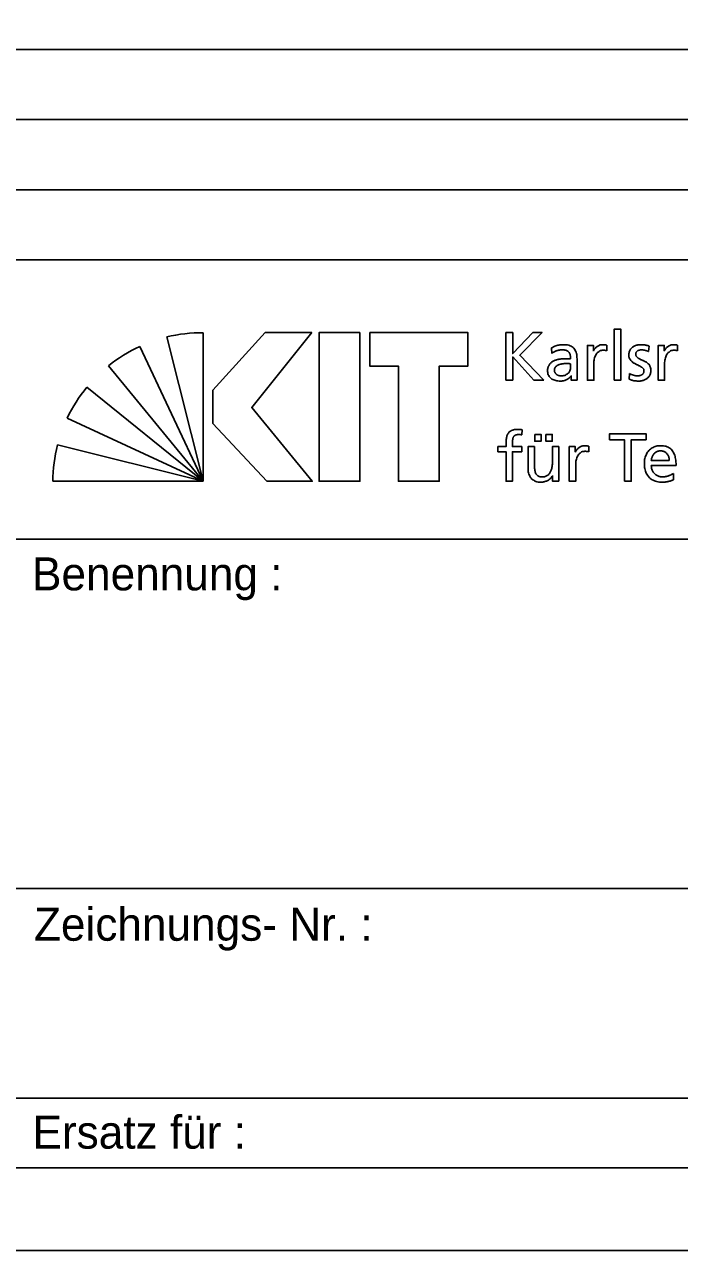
# Model space of a CAD drawing. Extents: x 0 to 210, y 0 to 148.
# Drawn here: x 188.16 to 198.08, y 0 to 18.56 of the extents above; entities that cross this region are included whole.
import ezdxf

# ---------------------------------------------------------------- set-up
doc = ezdxf.new("R2010")
doc.units = 0
doc.layers.add('90_Plankopf', color=7, linetype='Continuous')

msp = doc.modelspace()

# ---------------------------------------------------------------- linework, layer by layer
at = {"layer": '90_Plankopf'}
for p, q in [((164.53, 18.185), (209, 18.185)), ((164.53, 17.123), (209, 17.123)), ((164.53, 16.06), (209, 16.06)), ((164.53, 14.998), (209, 14.998)), ((164.53, 14.998), (209, 14.998)), ((190.319, 13.833), (190.87, 11.647)), ((190.87, 11.647), (190.87, 13.896)), ((195.452, 13.897), (195.452, 13.176)), ((190.87, 11.647), (189.908, 13.688)), ((196.145, 13.665), (196.15, 13.583)), ((196.982, 13.621), (196.982, 13.708)), ((197.614, 13.61), (197.622, 13.694)), ((198.053, 13.621), (198.053, 13.708)), ((189.436, 13.396), (190.87, 11.647)), ((196.433, 13.427), (196.433, 13.381)), ((196.53, 13.28), (196.53, 13.497)), ((197.324, 13.28), (197.319, 13.193)), ((190.87, 11.647), (189.108, 13.071)), ((195.452, 13.176), (195.556, 13.176)), ((195.876, 13.176), (196.027, 13.176)), ((188.81, 12.603), (190.87, 11.647)), ((195.693, 12.348), (195.697, 12.427)), ((190.87, 11.647), (188.664, 12.197)), ((196.707, 12.091), (196.707, 12.178)), ((197.927, 11.96), (197.654, 11.96)), ((197.654, 11.888), (198.03, 11.888)), ((197.989, 11.668), (197.989, 11.765)), ((188.591, 11.647), (190.87, 11.647)), ((188, 10.768), (209, 10.768)), ((188, 5.48), (209, 5.48)), ((188, 2.308), (209, 2.308)), ((209, 1.25), (164.53, 1.25)), ((167.45, 1.25), (209, 1.25)), ((167.45, 1.25), (209, 1.25))]:
    msp.add_line(p, q, dxfattribs=at)
for points in [[(0, 0), (210.25, 0), (210.25, 148.5), (0, 148.5)], [(6.25, 147.25), (209, 147.25), (209, 1.25), (6.25, 1.25)], [(192.517, 13.897), (191.809, 13.897), (191.018, 13.025), (191.018, 12.523), (191.834, 11.647), (192.521, 11.647), (191.606, 12.766)], [(193.243, 13.897), (193.243, 11.647), (192.625, 11.647), (192.625, 13.897)], [(193.391, 13.897), (193.391, 13.39), (193.825, 13.39), (193.825, 11.647), (194.443, 11.647), (194.443, 13.39), (194.877, 13.39), (194.877, 13.897)]]:
    msp.add_lwpolyline(points, close=True, dxfattribs=at)
for points in [[(197.095, 13.176), (197.192, 13.176), (197.192, 13.95), (197.095, 13.95), (197.095, 13.176)], [(196.027, 13.176), (195.662, 13.556), (196, 13.897), (195.863, 13.897), (195.556, 13.58), (195.556, 13.897), (195.452, 13.897)], [(196.78, 13.621), (196.778, 13.621), (196.778, 13.703), (196.688, 13.703), (196.688, 13.176), (196.785, 13.176), (196.785, 13.416)], [(197.852, 13.621), (197.85, 13.621), (197.85, 13.703), (197.759, 13.703), (197.759, 13.176), (197.856, 13.176), (197.856, 13.416)], [(195.556, 13.176), (195.556, 13.529), (195.876, 13.176)], [(196.441, 13.245), (196.443, 13.245), (196.443, 13.176), (196.534, 13.176)], [(195.889, 12.356), (195.889, 12.253), (195.986, 12.253), (195.986, 12.356), (195.889, 12.356)], [(196.058, 12.356), (196.058, 12.253), (196.155, 12.253), (196.155, 12.356), (196.058, 12.356)], [(197.248, 11.647), (197.351, 11.647), (197.351, 12.276), (197.575, 12.276), (197.575, 12.367), (197.024, 12.367), (197.024, 12.276), (197.248, 12.276), (197.248, 11.647)], [(195.456, 12.221), (195.456, 12.173), (195.332, 12.173), (195.332, 12.094), (195.456, 12.094), (195.456, 11.647), (195.553, 11.647), (195.553, 12.094), (195.692, 12.094), (195.692, 12.173), (195.553, 12.173), (195.553, 12.23)], [(195.885, 11.9), (195.885, 12.173), (195.788, 12.173), (195.788, 11.86)], [(196.254, 11.647), (196.254, 12.173), (196.157, 12.173), (196.157, 11.929)], [(196.506, 12.091), (196.504, 12.091), (196.504, 12.173), (196.413, 12.173), (196.413, 11.647), (196.51, 11.647), (196.51, 11.886)], [(196.158, 11.73), (196.16, 11.73), (196.16, 11.647), (196.254, 11.647)]]:
    msp.add_lwpolyline(points, dxfattribs=at)
for centre, start, end in [((190.862, 11.514), 89.8053, 103.1895), ((190.915, 11.529), 115.0126, 128.3968), ((190.954, 11.566), 140.7898, 154.174), ((190.973, 11.609), 165.7222, 179.1064)]:
    msp.add_arc(centre, 2.382, start, end, dxfattribs=at)
for points in [[(196.53, 13.497), (196.53, 13.545), (196.523, 13.585), (196.508, 13.617), (196.494, 13.65), (196.471, 13.674), (196.44, 13.69), (196.409, 13.707), (196.368, 13.715), (196.318, 13.715), (196.285, 13.715), (196.253, 13.71), (196.224, 13.701), (196.195, 13.692), (196.169, 13.68), (196.145, 13.665)], [(196.15, 13.583), (196.163, 13.594), (196.178, 13.604), (196.195, 13.611), (196.211, 13.62), (196.229, 13.626), (196.247, 13.63), (196.266, 13.634), (196.284, 13.637), (196.303, 13.637), (196.335, 13.637), (196.36, 13.631), (196.379, 13.621), (196.399, 13.611), (196.412, 13.596), (196.42, 13.575), (196.429, 13.555), (196.433, 13.53), (196.433, 13.499)], [(196.982, 13.708), (196.975, 13.709), (196.968, 13.71), (196.962, 13.712), (196.956, 13.713), (196.949, 13.713), (196.942, 13.714), (196.935, 13.715), (196.927, 13.715), (196.918, 13.715), (196.899, 13.715), (196.881, 13.711), (196.863, 13.703), (196.845, 13.695), (196.829, 13.684), (196.815, 13.67), (196.801, 13.656), (196.789, 13.639), (196.78, 13.621)], [(196.785, 13.416), (196.785, 13.46), (196.791, 13.498), (196.802, 13.53), (196.814, 13.562), (196.831, 13.587), (196.852, 13.604), (196.874, 13.621), (196.899, 13.63), (196.928, 13.63), (196.936, 13.631), (196.945, 13.63), (196.954, 13.629), (196.964, 13.627), (196.973, 13.625), (196.982, 13.621)], [(197.622, 13.694), (197.604, 13.7), (197.584, 13.705), (197.565, 13.709), (197.545, 13.713), (197.524, 13.715), (197.502, 13.715), (197.476, 13.715), (197.451, 13.712), (197.429, 13.705), (197.406, 13.698), (197.387, 13.688), (197.37, 13.675), (197.353, 13.662), (197.34, 13.645), (197.33, 13.625), (197.321, 13.604), (197.316, 13.58), (197.316, 13.553), (197.316, 13.532), (197.321, 13.514), (197.329, 13.498), (197.337, 13.483), (197.348, 13.47), (197.361, 13.459), (197.375, 13.447), (197.39, 13.437), (197.406, 13.429), (197.422, 13.42), (197.438, 13.412), (197.454, 13.404), (197.471, 13.397), (197.485, 13.389), (197.499, 13.38), (197.512, 13.373), (197.523, 13.363), (197.532, 13.353), (197.54, 13.343), (197.544, 13.331), (197.544, 13.318), (197.544, 13.304), (197.541, 13.292), (197.535, 13.282), (197.529, 13.272), (197.521, 13.265), (197.511, 13.259), (197.501, 13.253), (197.491, 13.249), (197.479, 13.246), (197.468, 13.244), (197.456, 13.242), (197.445, 13.242), (197.435, 13.242), (197.424, 13.244), (197.41, 13.247), (197.396, 13.249), (197.381, 13.253), (197.366, 13.259), (197.351, 13.265), (197.337, 13.271), (197.324, 13.28)], [(197.319, 13.193), (197.342, 13.181), (197.365, 13.174), (197.389, 13.17), (197.414, 13.166), (197.439, 13.164), (197.464, 13.164), (197.487, 13.164), (197.51, 13.167), (197.532, 13.174), (197.554, 13.18), (197.573, 13.191), (197.591, 13.204), (197.608, 13.217), (197.622, 13.234), (197.632, 13.255), (197.642, 13.276), (197.647, 13.3), (197.647, 13.328), (197.647, 13.352), (197.643, 13.372), (197.635, 13.389), (197.626, 13.406), (197.616, 13.42), (197.602, 13.431), (197.589, 13.443), (197.574, 13.453), (197.557, 13.461), (197.541, 13.469), (197.525, 13.477), (197.509, 13.484), (197.493, 13.491), (197.478, 13.499), (197.464, 13.507), (197.451, 13.515), (197.44, 13.524), (197.432, 13.534), (197.424, 13.545), (197.419, 13.557), (197.419, 13.573), (197.419, 13.587), (197.424, 13.599), (197.432, 13.609), (197.441, 13.618), (197.452, 13.625), (197.466, 13.63), (197.48, 13.634), (197.495, 13.637), (197.512, 13.637), (197.518, 13.637), (197.526, 13.636), (197.535, 13.634), (197.544, 13.633), (197.553, 13.631), (197.564, 13.628), (197.574, 13.626), (197.583, 13.623), (197.592, 13.62), (197.601, 13.616), (197.609, 13.613), (197.614, 13.61)], [(198.053, 13.708), (198.046, 13.709), (198.04, 13.71), (198.034, 13.712), (198.027, 13.713), (198.021, 13.713), (198.014, 13.714), (198.007, 13.715), (197.998, 13.715), (197.989, 13.715), (197.97, 13.715), (197.952, 13.711), (197.934, 13.703), (197.917, 13.695), (197.901, 13.684), (197.886, 13.67), (197.872, 13.656), (197.86, 13.639), (197.852, 13.621)], [(197.856, 13.416), (197.856, 13.46), (197.862, 13.498), (197.874, 13.53), (197.886, 13.562), (197.902, 13.587), (197.923, 13.604), (197.945, 13.621), (197.97, 13.63), (197.999, 13.63), (198.008, 13.631), (198.016, 13.63), (198.026, 13.629), (198.035, 13.627), (198.044, 13.625), (198.053, 13.621)], [(196.433, 13.499), (196.42, 13.5), (196.408, 13.501), (196.397, 13.501), (196.386, 13.501), (196.376, 13.501), (196.365, 13.501), (196.354, 13.501), (196.342, 13.501), (196.329, 13.501), (196.309, 13.501), (196.288, 13.5), (196.266, 13.496), (196.243, 13.492), (196.221, 13.487), (196.2, 13.478), (196.179, 13.47), (196.16, 13.46), (196.142, 13.446), (196.125, 13.433), (196.111, 13.416), (196.101, 13.397), (196.09, 13.377), (196.085, 13.354), (196.085, 13.328), (196.085, 13.29), (196.094, 13.259), (196.11, 13.235), (196.126, 13.211), (196.149, 13.193), (196.177, 13.181), (196.206, 13.17), (196.24, 13.164), (196.278, 13.164), (196.3, 13.164), (196.32, 13.167), (196.338, 13.172), (196.355, 13.177), (196.371, 13.184), (196.384, 13.192), (196.398, 13.2), (196.409, 13.209), (196.418, 13.218), (196.428, 13.228), (196.435, 13.236), (196.441, 13.245)], [(196.433, 13.381), (196.433, 13.354), (196.427, 13.331), (196.416, 13.31), (196.405, 13.289), (196.388, 13.273), (196.367, 13.261), (196.345, 13.249), (196.318, 13.243), (196.286, 13.242), (196.275, 13.242), (196.264, 13.244), (196.252, 13.248), (196.241, 13.252), (196.23, 13.257), (196.22, 13.264), (196.211, 13.272), (196.203, 13.281), (196.197, 13.291), (196.191, 13.302), (196.188, 13.314), (196.188, 13.328), (196.188, 13.347), (196.193, 13.362), (196.202, 13.374), (196.211, 13.387), (196.223, 13.396), (196.237, 13.404), (196.252, 13.411), (196.267, 13.417), (196.284, 13.42), (196.3, 13.424), (196.316, 13.426), (196.332, 13.428), (196.347, 13.429), (196.36, 13.429), (196.371, 13.429), (196.381, 13.429), (196.391, 13.429), (196.402, 13.428), (196.412, 13.428), (196.422, 13.427), (196.433, 13.427)], [(196.534, 13.176), (196.533, 13.181), (196.532, 13.188), (196.532, 13.197), (196.531, 13.205), (196.531, 13.216), (196.53, 13.23), (196.53, 13.243), (196.53, 13.26), (196.53, 13.28)], [(195.697, 12.427), (195.688, 12.428), (195.678, 12.43), (195.667, 12.431), (195.656, 12.432), (195.645, 12.433), (195.632, 12.433), (195.597, 12.433), (195.568, 12.428), (195.544, 12.418), (195.521, 12.408), (195.503, 12.394), (195.491, 12.375), (195.478, 12.356), (195.469, 12.334), (195.464, 12.308), (195.458, 12.282), (195.456, 12.253), (195.456, 12.221)], [(195.553, 12.23), (195.553, 12.247), (195.554, 12.264), (195.556, 12.279), (195.558, 12.294), (195.562, 12.307), (195.569, 12.319), (195.575, 12.33), (195.585, 12.339), (195.597, 12.345), (195.61, 12.351), (195.626, 12.354), (195.647, 12.354), (195.655, 12.354), (195.664, 12.354), (195.672, 12.353), (195.68, 12.352), (195.688, 12.35), (195.693, 12.348)], [(196.707, 12.178), (196.7, 12.179), (196.693, 12.181), (196.688, 12.182), (196.681, 12.183), (196.675, 12.184), (196.667, 12.184), (196.661, 12.185), (196.652, 12.185), (196.643, 12.185), (196.624, 12.185), (196.606, 12.181), (196.588, 12.173), (196.571, 12.165), (196.555, 12.154), (196.54, 12.14), (196.526, 12.126), (196.514, 12.11), (196.506, 12.091)], [(196.51, 11.886), (196.51, 11.93), (196.516, 11.968), (196.528, 12), (196.539, 12.032), (196.556, 12.057), (196.577, 12.074), (196.599, 12.092), (196.624, 12.1), (196.653, 12.1), (196.662, 12.101), (196.67, 12.1), (196.68, 12.099), (196.689, 12.097), (196.698, 12.095), (196.707, 12.091)], [(198.03, 11.888), (198.03, 11.931), (198.026, 11.97), (198.018, 12.006), (198.01, 12.042), (197.997, 12.073), (197.979, 12.1), (197.961, 12.127), (197.938, 12.148), (197.908, 12.162), (197.878, 12.177), (197.841, 12.185), (197.797, 12.185), (197.76, 12.185), (197.726, 12.178), (197.696, 12.166), (197.666, 12.152), (197.64, 12.134), (197.618, 12.111), (197.597, 12.087), (197.58, 12.059), (197.569, 12.026), (197.557, 11.994), (197.551, 11.958), (197.551, 11.919), (197.551, 11.876), (197.556, 11.837), (197.567, 11.802), (197.578, 11.767), (197.595, 11.737), (197.617, 11.712), (197.639, 11.687), (197.668, 11.668), (197.702, 11.655), (197.736, 11.641), (197.777, 11.634), (197.823, 11.634), (197.852, 11.634), (197.876, 11.636), (197.897, 11.64), (197.917, 11.644), (197.934, 11.648), (197.949, 11.653), (197.964, 11.659), (197.977, 11.664), (197.989, 11.668)], [(197.654, 11.96), (197.656, 11.977), (197.66, 11.995), (197.666, 12.012), (197.672, 12.029), (197.681, 12.045), (197.692, 12.059), (197.703, 12.073), (197.717, 12.085), (197.734, 12.093), (197.751, 12.102), (197.772, 12.107), (197.795, 12.107), (197.816, 12.107), (197.835, 12.103), (197.851, 12.095), (197.867, 12.088), (197.881, 12.077), (197.892, 12.064), (197.903, 12.05), (197.912, 12.035), (197.918, 12.017), (197.924, 11.999), (197.927, 11.981), (197.927, 11.96)], [(196.157, 11.929), (196.157, 11.897), (196.154, 11.868), (196.147, 11.841), (196.141, 11.815), (196.131, 11.792), (196.118, 11.773), (196.105, 11.754), (196.088, 11.739), (196.068, 11.728), (196.048, 11.718), (196.024, 11.713), (195.997, 11.713), (195.969, 11.714), (195.947, 11.722), (195.93, 11.736), (195.914, 11.75), (195.902, 11.771), (195.895, 11.798), (195.889, 11.825), (195.885, 11.859), (195.885, 11.9)], [(197.989, 11.765), (197.983, 11.76), (197.975, 11.755), (197.963, 11.749), (197.952, 11.743), (197.939, 11.737), (197.924, 11.732), (197.909, 11.726), (197.893, 11.722), (197.876, 11.718), (197.86, 11.715), (197.844, 11.713), (197.827, 11.713), (197.804, 11.713), (197.782, 11.717), (197.762, 11.725), (197.741, 11.734), (197.722, 11.746), (197.706, 11.761), (197.69, 11.777), (197.677, 11.795), (197.668, 11.817), (197.659, 11.838), (197.654, 11.862), (197.654, 11.888)], [(195.788, 11.86), (195.788, 11.813), (195.795, 11.772), (195.809, 11.739), (195.823, 11.705), (195.845, 11.679), (195.874, 11.661), (195.903, 11.644), (195.94, 11.634), (195.986, 11.634), (196.01, 11.634), (196.034, 11.638), (196.056, 11.646), (196.079, 11.653), (196.099, 11.665), (196.117, 11.679), (196.134, 11.693), (196.148, 11.71), (196.158, 11.73)]]:
    msp.add_open_spline(points, degree=3, dxfattribs=at)

# ---------------------------------------------------------------- texts
for s, p in [('Benennung :', (188.278, 9.995)), ('Zeichnungs- Nr. :', (188.307, 4.69)), ('Ersatz für :', (188.285, 1.542))]:
    msp.add_text(s, height=0.5, dxfattribs=at).set_placement(p)

doc.saveas('drawing.dxf')
